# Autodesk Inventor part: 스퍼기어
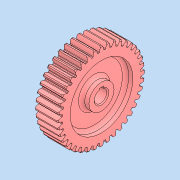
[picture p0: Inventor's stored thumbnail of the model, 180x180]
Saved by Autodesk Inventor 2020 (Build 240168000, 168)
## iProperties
Created: 2024-11
Part Number: 스퍼기어
Material: 강철, 탄소
Document SubType Name: Modeling
Designer: 1강의실14
Density: 7.85 g/cm^3
Appearance: 기본값
Author: jhkim
Sending System: Autodesk Inventor 2025
Preprocessor: ST-DEVELOPER v20
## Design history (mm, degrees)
node "스퍼기어1"
node "솔리드2"
node "솔리드1"
